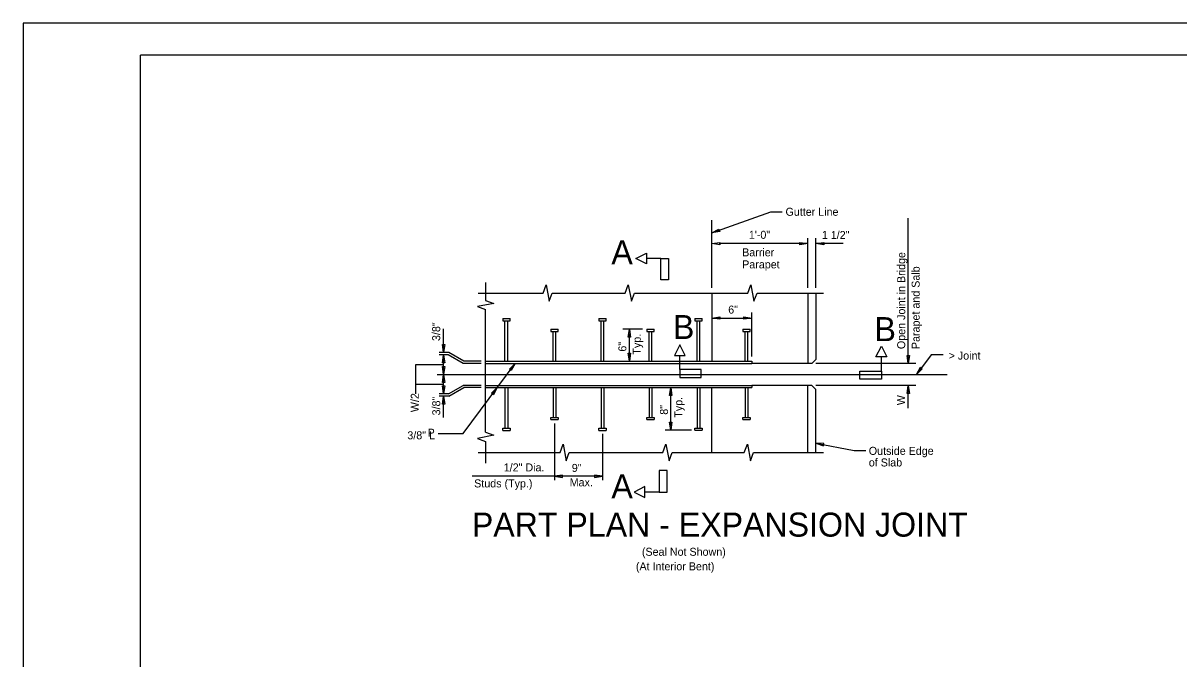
# Model space of a CAD drawing. Extents: x -125.5 to -89.4, y -5.1 to 16.9.
# Drawn here: x -125.53 to -107.48, y 7.01 to 16.93 of the extents above; entities that cross this region are included whole.
import ezdxf

# ---------------------------------------------------------------- set-up
doc = ezdxf.new("R2010")
doc.units = 0
for name, color, linetype in [('BR_AUTO DIMENSION', 7, 'Continuous'), ('BR_BORDER LINES', 7, 'Continuous'), ('BR_CENTER LINES', 7, 'Continuous'), ('BR_CONCRETE', 7, 'Continuous'), ('BR_STRUCTURAL STEEL', 7, 'Continuous'), ('BR_TABLE LINES', 7, 'Continuous'), ('BR_TEXT', 7, 'Continuous'), ('Level 31', 7, 'Continuous')]:
    doc.layers.add(name, color=color, linetype=linetype)

msp = doc.modelspace()

# ---------------------------------------------------------------- linework, layer by layer
at = {"layer": 'BR_AUTO DIMENSION'}
for p, q in [((-114.775, 13.659), (-113.854, 13.987)), ((-113.854, 13.987), (-113.674, 13.987)), ((-114.775, 12.801), (-114.775, 13.861)), ((-111.707, 11.623), (-111.707, 13.89)), ((-113.275, 13.242), (-113.275, 13.575)), ((-113.15, 12.8), (-113.15, 13.575)), ((-113.275, 13.493), (-114.661, 13.493)), ((-113.275, 12.8), (-113.275, 13.419)), ((-112.721, 13.493), (-113.15, 13.493)), ((-113.275, 12.8), (-113.275, 12.932)), ((-114.775, 12.331), (-114.148, 12.331)), ((-114.148, 11.733), (-114.148, 12.416)), ((-118.966, 11.791), (-118.966, 12.162)), ((-115.859, 12.156), (-116.165, 12.156)), ((-116.061, 11.656), (-116.061, 12.089)), ((-118.883, 11.791), (-119.033, 11.791)), ((-118.892, 11.757), (-119.033, 11.757)), ((-118.966, 11.451), (-118.966, 11.757)), ((-118.657, 11.623), (-118.892, 11.757)), ((-118.648, 11.656), (-118.883, 11.791)), ((-111.351, 11.755), (-111.576, 11.451)), ((-111.16, 11.755), (-111.351, 11.755)), ((-119.399, 11.607), (-118.966, 11.607)), ((-119.399, 11.15), (-119.399, 11.607)), ((-118.66, 10.528), (-117.847, 11.623)), ((-118.376, 11.623), (-118.657, 11.623)), ((-118.376, 11.656), (-118.648, 11.656)), ((-111.586, 11.623), (-113.15, 11.623)), ((-118.966, 11.146), (-118.966, 11.451)), ((-119.399, 11.301), (-118.966, 11.301)), ((-118.89, 11.146), (-118.657, 11.279)), ((-118.881, 11.112), (-118.648, 11.245)), ((-118.376, 11.279), (-118.657, 11.279)), ((-118.376, 11.245), (-118.648, 11.245)), ((-115.417, 10.647), (-115.417, 11.245)), ((-111.586, 11.279), (-113.15, 11.279)), ((-111.707, 10.922), (-111.707, 11.279)), ((-118.89, 11.146), (-119.033, 11.146)), ((-118.881, 11.112), (-119.033, 11.112)), ((-118.966, 10.777), (-118.966, 11.112)), ((-117.233, 10.687), (-117.233, 9.799)), ((-119.048, 10.528), (-118.66, 10.528)), ((-116.483, 10.523), (-116.483, 9.799)), ((-115.095, 10.579), (-115.505, 10.579)), ((-113.15, 10.378), (-112.553, 10.264)), ((-112.553, 10.264), (-112.372, 10.264)), ((-116.483, 9.861), (-118.516, 9.861)), ((-117.233, 9.861), (-117.233, 9.861))]:
    msp.add_line(p, q, dxfattribs=at)
for points in [[(-114.651, 13.684), (-114.775, 13.659), (-114.664, 13.719)], [(-114.65, 13.474), (-114.775, 13.493), (-114.65, 13.511)], [(-113.4, 13.511), (-113.275, 13.493), (-113.4, 13.474)], [(-113.025, 13.474), (-113.15, 13.493), (-113.025, 13.511)], [(-114.65, 12.313), (-114.775, 12.331), (-114.65, 12.35)], [(-114.273, 12.35), (-114.148, 12.331), (-114.273, 12.313)], [(-114.273, 12.35), (-114.148, 12.331), (-114.273, 12.313)], [(-116.08, 12.031), (-116.061, 12.156), (-116.043, 12.031)], [(-116.08, 12.031), (-116.061, 12.156), (-116.043, 12.031)], [(-118.947, 11.916), (-118.966, 11.791), (-118.984, 11.916)], [(-118.984, 11.632), (-118.966, 11.757), (-118.947, 11.632)], [(-116.043, 11.781), (-116.061, 11.656), (-116.08, 11.781)], [(-111.688, 11.748), (-111.707, 11.623), (-111.725, 11.748)], [(-118.947, 11.576), (-118.966, 11.451), (-118.984, 11.576)], [(-117.937, 11.533), (-117.847, 11.623), (-117.907, 11.511)], [(-111.487, 11.54), (-111.576, 11.451), (-111.517, 11.563)], [(-118.984, 11.326), (-118.966, 11.451), (-118.947, 11.326)], [(-118.947, 11.271), (-118.966, 11.146), (-118.984, 11.271)], [(-118.218, 11.156), (-118.128, 11.245), (-118.187, 11.134)], [(-115.436, 11.12), (-115.417, 11.245), (-115.398, 11.12)], [(-111.725, 11.154), (-111.707, 11.279), (-111.688, 11.154)], [(-118.984, 10.987), (-118.966, 11.112), (-118.947, 10.987)], [(-115.398, 10.704), (-115.417, 10.579), (-115.436, 10.704)], [(-113.023, 10.373), (-113.15, 10.378), (-113.03, 10.336)], [(-117.108, 9.88), (-117.233, 9.861), (-117.108, 9.843)], [(-116.608, 9.843), (-116.483, 9.861), (-116.608, 9.88)], [(-116.608, 9.843), (-116.483, 9.861), (-116.608, 9.88)]]:
    msp.add_lwpolyline(points, close=True, dxfattribs=at)
at = {"layer": 'BR_BORDER LINES'}
for p in [(-90.033, 16.434), (-123.699, -4.566)]:
    msp.add_line(p, (-123.699, 16.434), dxfattribs=at)
at = {"layer": 'BR_CENTER LINES'}
for p, q in [((-118.309, 12.885), (-118.309, 12.607)), ((-118.425, 12.72), (-117.412, 12.72)), ((-117.268, 12.72), (-116.128, 12.72)), ((-115.983, 12.72), (-114.214, 12.72)), ((-114.069, 12.72), (-113.029, 12.72)), ((-118.309, 10.549), (-118.309, 12.462)), ((-119.064, 11.451), (-118.83, 11.451)), ((-118.83, 11.451), (-117.913, 11.451)), ((-117.913, 11.451), (-111.098, 11.451)), ((-118.309, 10.404), (-118.309, 10.066)), ((-118.425, 10.231), (-117.145, 10.231)), ((-117.001, 10.231), (-115.539, 10.231)), ((-115.394, 10.231), (-114.268, 10.231)), ((-114.124, 10.231), (-113.029, 10.231))]:
    msp.add_line(p, q, dxfattribs=at)
for points in [[(-117.412, 12.72), (-117.364, 12.849), (-117.316, 12.592), (-117.268, 12.72)], [(-116.128, 12.72), (-116.08, 12.849), (-116.031, 12.592), (-115.983, 12.72)], [(-114.214, 12.72), (-114.166, 12.849), (-114.118, 12.592), (-114.069, 12.72)], [(-118.309, 12.607), (-118.18, 12.559), (-118.437, 12.51), (-118.309, 12.462)], [(-118.309, 10.549), (-118.18, 10.5), (-118.437, 10.452), (-118.309, 10.404)], [(-117.145, 10.231), (-117.097, 10.36), (-117.049, 10.103), (-117.001, 10.231)], [(-115.539, 10.231), (-115.491, 10.36), (-115.443, 10.103), (-115.394, 10.231)], [(-114.268, 10.231), (-114.22, 10.36), (-114.172, 10.103), (-114.124, 10.231)]]:
    msp.add_lwpolyline(points, dxfattribs=at)
at = {"layer": 'BR_CONCRETE'}
for p, q in [((-114.775, 12.72), (-114.775, 11.656)), ((-113.275, 12.72), (-113.275, 11.623)), ((-113.15, 12.72), (-113.15, 11.686)), ((-113.213, 11.623), (-114.148, 11.623)), ((-113.15, 11.686), (-113.213, 11.623)), ((-114.775, 10.231), (-114.775, 11.245)), ((-113.212, 11.279), (-114.148, 11.279)), ((-113.275, 10.231), (-113.275, 11.279)), ((-113.15, 11.216), (-113.212, 11.279)), ((-113.15, 10.231), (-113.15, 11.216))]:
    msp.add_line(p, q, dxfattribs=at)
at = {"layer": 'BR_STRUCTURAL STEEL'}
for p, q in [((-118.039, 12.323), (-117.926, 12.323)), ((-118.039, 12.323), (-118.039, 12.289)), ((-118.039, 12.289), (-117.926, 12.289)), ((-118.006, 12.323), (-117.994, 12.323)), ((-118.006, 11.656), (-118.006, 12.289)), ((-117.96, 11.656), (-117.96, 12.289)), ((-117.926, 12.289), (-117.926, 12.323)), ((-116.539, 12.323), (-116.426, 12.323)), ((-116.539, 12.323), (-116.539, 12.289)), ((-116.539, 12.289), (-116.426, 12.289)), ((-116.506, 12.323), (-116.494, 12.323)), ((-116.506, 11.656), (-116.506, 12.289)), ((-116.46, 11.656), (-116.46, 12.289)), ((-116.426, 12.289), (-116.426, 12.323)), ((-115.039, 12.323), (-114.926, 12.323)), ((-115.039, 12.323), (-115.039, 12.289)), ((-115.039, 12.289), (-114.926, 12.289)), ((-115.006, 11.656), (-115.006, 12.289)), ((-115.005, 12.323), (-114.993, 12.323)), ((-114.96, 11.656), (-114.96, 12.289)), ((-114.926, 12.289), (-114.926, 12.323)), ((-117.289, 12.156), (-117.176, 12.156)), ((-117.289, 12.156), (-117.289, 12.123)), ((-117.289, 12.123), (-117.176, 12.123)), ((-117.255, 11.656), (-117.255, 12.123)), ((-117.21, 11.656), (-117.21, 12.123)), ((-117.176, 12.123), (-117.176, 12.156)), ((-115.79, 12.156), (-115.677, 12.156)), ((-115.79, 12.156), (-115.79, 12.123)), ((-115.79, 12.123), (-115.677, 12.123)), ((-115.756, 11.656), (-115.756, 12.123)), ((-115.711, 11.656), (-115.711, 12.123)), ((-115.677, 12.123), (-115.677, 12.156)), ((-114.29, 12.156), (-114.177, 12.156)), ((-114.29, 12.156), (-114.29, 12.123)), ((-114.29, 12.123), (-114.177, 12.123)), ((-114.256, 11.656), (-114.256, 12.123)), ((-114.211, 11.656), (-114.211, 12.123)), ((-114.177, 12.123), (-114.177, 12.156)), ((-118.309, 11.656), (-118.129, 11.656)), ((-118.309, 11.623), (-114.775, 11.623)), ((-118.129, 11.656), (-114.775, 11.656)), ((-114.775, 11.656), (-114.148, 11.656)), ((-114.775, 11.623), (-114.148, 11.623)), ((-114.148, 11.656), (-114.148, 11.623)), ((-118.309, 11.279), (-114.775, 11.279)), ((-118.309, 11.245), (-114.775, 11.245)), ((-118.006, 11.245), (-118.006, 10.612)), ((-117.96, 11.245), (-117.96, 10.612)), ((-117.255, 11.245), (-117.255, 10.779)), ((-117.21, 11.245), (-117.21, 10.779)), ((-116.506, 11.245), (-116.506, 10.612)), ((-116.46, 11.245), (-116.46, 10.612)), ((-115.756, 11.246), (-115.756, 10.779)), ((-115.711, 11.246), (-115.711, 10.779)), ((-115.52, 11.245), (-114.775, 11.245)), ((-115.006, 11.246), (-115.006, 10.613)), ((-114.96, 11.246), (-114.96, 10.613)), ((-114.775, 11.279), (-114.148, 11.279)), ((-114.775, 11.245), (-114.148, 11.245)), ((-114.256, 11.246), (-114.256, 10.779)), ((-114.211, 11.246), (-114.211, 10.779)), ((-114.148, 11.279), (-114.148, 11.245)), ((-117.289, 10.745), (-117.289, 10.779)), ((-117.289, 10.779), (-117.176, 10.779)), ((-117.289, 10.745), (-117.176, 10.745)), ((-117.255, 10.745), (-117.244, 10.745)), ((-117.176, 10.779), (-117.176, 10.745)), ((-115.79, 10.746), (-115.79, 10.779)), ((-115.79, 10.779), (-115.677, 10.779)), ((-115.79, 10.746), (-115.677, 10.746)), ((-115.677, 10.779), (-115.677, 10.746)), ((-114.29, 10.746), (-114.29, 10.779)), ((-114.29, 10.779), (-114.177, 10.779)), ((-114.29, 10.746), (-114.177, 10.746)), ((-114.177, 10.779), (-114.177, 10.746)), ((-118.039, 10.578), (-118.039, 10.612)), ((-118.039, 10.612), (-117.926, 10.612)), ((-118.039, 10.578), (-117.926, 10.578)), ((-118.006, 10.578), (-117.994, 10.578)), ((-117.926, 10.612), (-117.926, 10.578)), ((-116.539, 10.578), (-116.539, 10.612)), ((-116.539, 10.612), (-116.426, 10.612)), ((-116.539, 10.578), (-116.426, 10.578)), ((-116.506, 10.578), (-116.494, 10.578)), ((-116.426, 10.612), (-116.426, 10.578)), ((-115.039, 10.579), (-115.039, 10.613)), ((-115.039, 10.613), (-114.926, 10.613)), ((-115.039, 10.579), (-114.926, 10.579)), ((-115.005, 10.579), (-114.993, 10.579)), ((-114.926, 10.613), (-114.926, 10.579))]:
    msp.add_line(p, q, dxfattribs=at)
at = {"layer": 'BR_TABLE LINES'}
for p, q in [((-115.573, 13.261), (-115.795, 13.261)), ((-115.275, 11.526), (-115.275, 11.748)), ((-112.127, 11.502), (-112.127, 11.724)), ((-115.597, 9.615), (-115.819, 9.615))]:
    msp.add_line(p, q, dxfattribs=at)
for points in [[(-115.795, 13.178), (-115.962, 13.261), (-115.795, 13.345)], [(-115.451, 12.928), (-115.573, 12.928), (-115.573, 13.261), (-115.451, 13.261)], [(-115.192, 11.748), (-115.275, 11.915), (-115.358, 11.748)], [(-112.211, 11.724), (-112.127, 11.89), (-112.044, 11.724)], [(-114.942, 11.403), (-114.942, 11.526), (-115.275, 11.526), (-115.275, 11.403)], [(-112.461, 11.379), (-112.461, 11.502), (-112.127, 11.502), (-112.127, 11.379)], [(-115.475, 9.949), (-115.597, 9.949), (-115.597, 9.615), (-115.475, 9.615)], [(-115.819, 9.699), (-115.986, 9.615), (-115.819, 9.532)]]:
    msp.add_lwpolyline(points, close=True, dxfattribs=at)
at = {"layer": 'Level 31'}
msp.add_lwpolyline([(-125.533, -5.066), (-89.533, -5.066), (-89.533, 16.934), (-125.533, 16.934)], close=True, dxfattribs=at)

# ---------------------------------------------------------------- texts
at = {"layer": 'BR_TEXT'}
for s, height, p in [('Gutter Line', 0.125, (-113.624, 13.927)), ('A', 0.375, (-116.344, 13.171)), ('1\'-0"', 0.125, (-114.197, 13.568)), ('1 1/2"', 0.125, (-113.056, 13.565)), ('Barrier', 0.125, (-114.301, 13.294)), ('Parapet', 0.125, (-114.301, 13.106)), ('6"', 0.125, (-114.519, 12.4)), ('B', 0.375, (-115.383, 12.003)), ('B', 0.375, (-112.234, 11.97)), ('> Joint', 0.125, (-111.076, 11.682)), ('3/8" L', 0.125, (-119.531, 10.438)), ('P', 0.125, (-119.214, 10.478)), ('Outside Edge', 0.125, (-112.323, 10.195)), ('of Slab', 0.125, (-112.323, 10.014)), ('1/2" Dia.', 0.125, (-118.025, 9.937)), ('9" ', 0.125, (-116.962, 9.929)), ('Studs (Typ.)', 0.125, (-118.487, 9.687)), ('Max.', 0.125, (-116.995, 9.704)), ('A', 0.375, (-116.344, 9.518)), ('PART PLAN - EXPANSION JOINT', 0.375, (-118.523, 8.919)), ('(Seal Not Shown)', 0.125, (-115.867, 8.62)), ('(At Interior Bent)', 0.125, (-115.961, 8.393))]:
    msp.add_text(s, height=height, dxfattribs=at).set_placement(p)
for s, p in [('Open Joint in Bridge', (-111.754, 11.846)), ('Parapet and Salb', (-111.529, 11.846)), ('3/8"', (-119.018, 11.972)), (' 6"', (-116.11, 11.76)), ('Typ.', (-115.885, 11.76)), ('W/2', (-119.352, 10.862)), ('3/8"', (-119.017, 10.811)), ('Typ.', (-115.235, 10.775)), ('W', (-111.758, 10.97)), (' 8"', (-115.46, 10.775))]:
    msp.add_text(s, height=0.125, rotation=90, dxfattribs=at).set_placement(p)

doc.saveas('drawing.dxf')
